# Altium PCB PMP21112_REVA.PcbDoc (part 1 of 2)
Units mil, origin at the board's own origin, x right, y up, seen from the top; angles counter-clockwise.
Board outline 3800 x 2750 mil, 4 copper layers (Top Layer, Signal Layer 1, Signal Layer 2, Bottom Layer), stack 68.2 mil thick; 110 components, 47 nets, 341 pads, 287 vias.
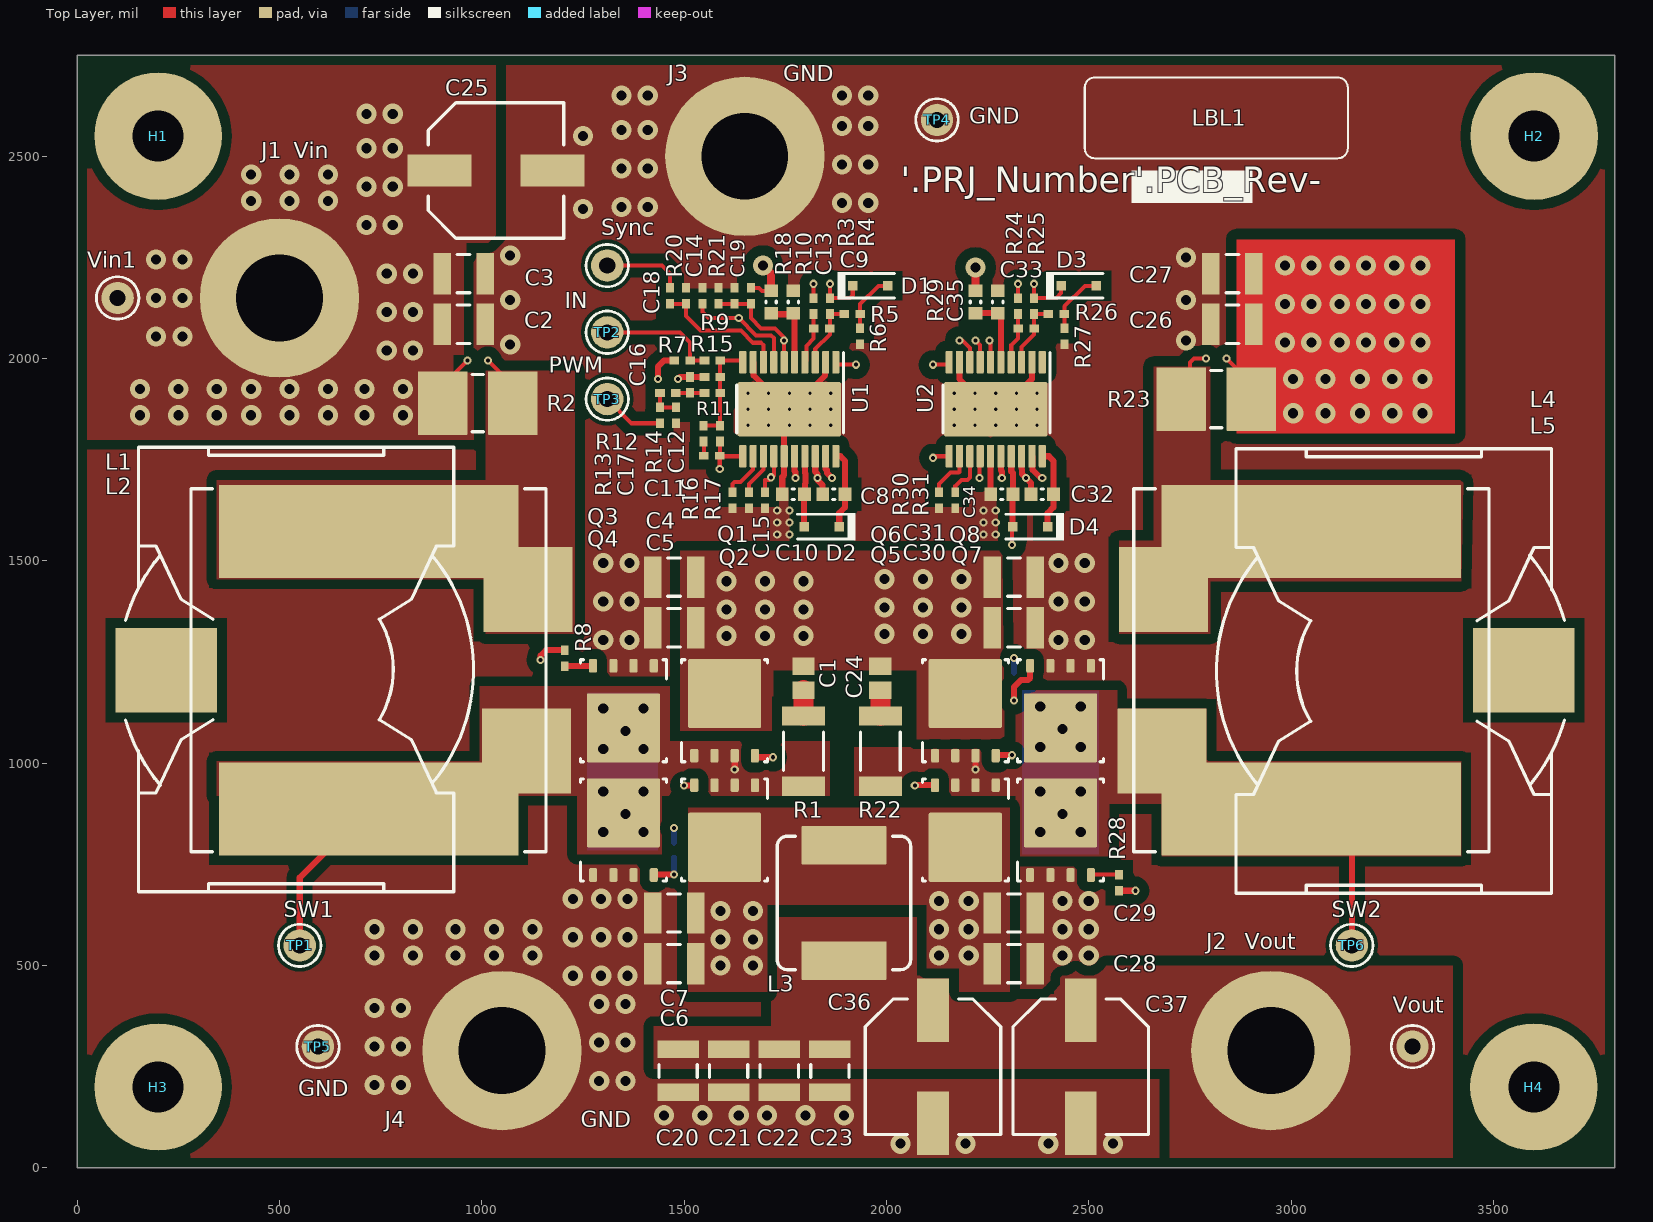
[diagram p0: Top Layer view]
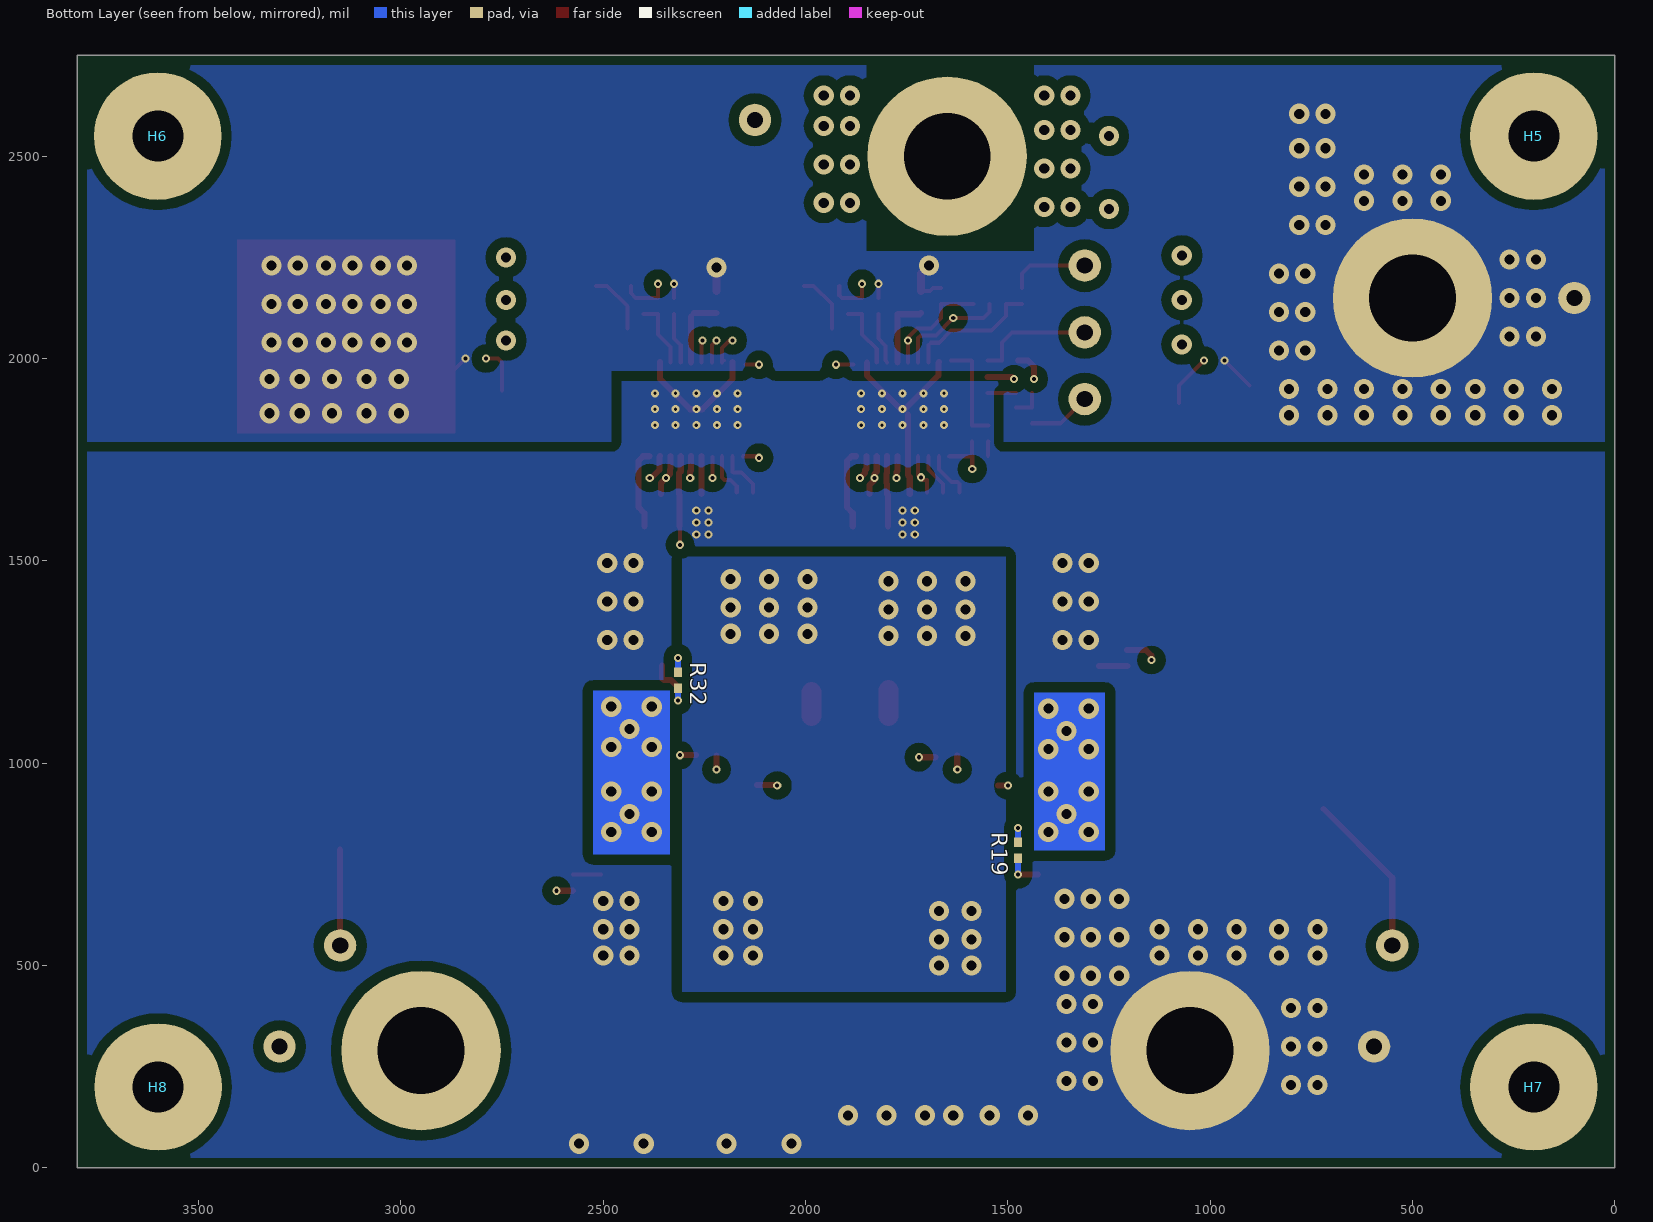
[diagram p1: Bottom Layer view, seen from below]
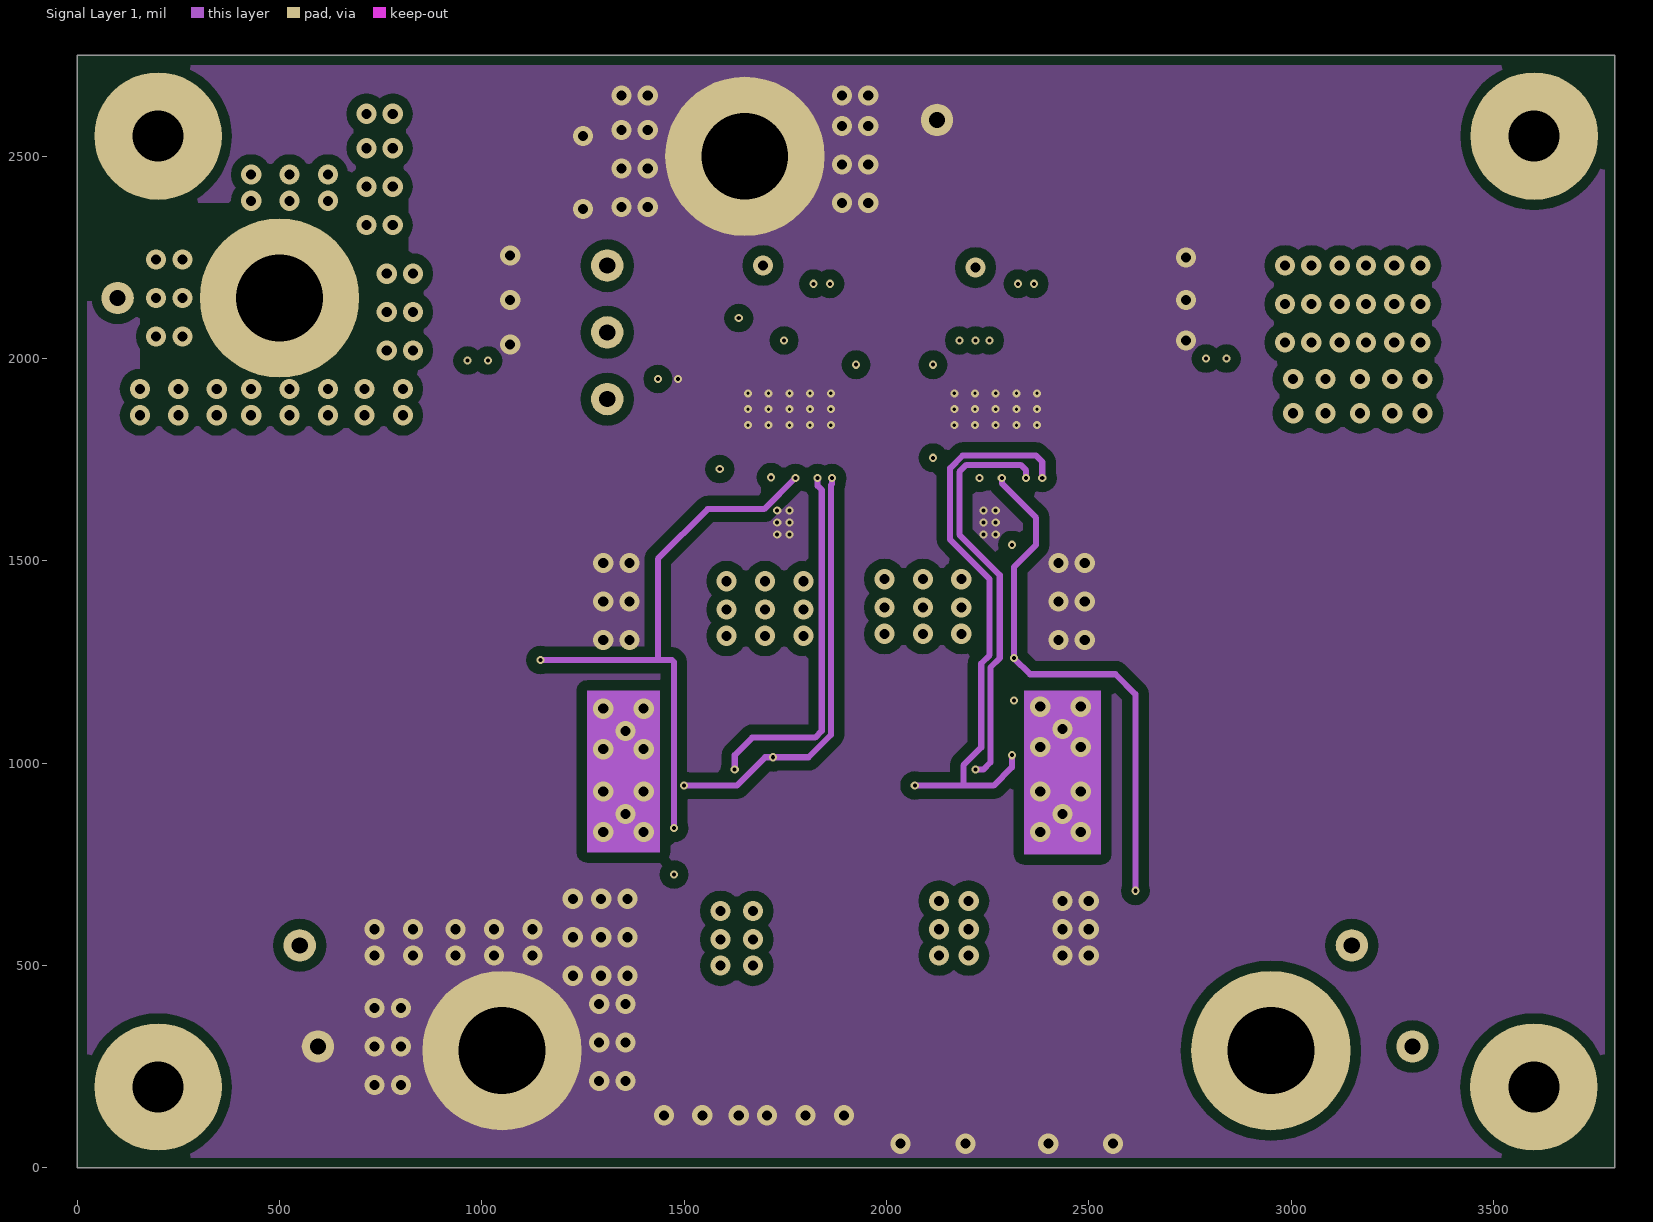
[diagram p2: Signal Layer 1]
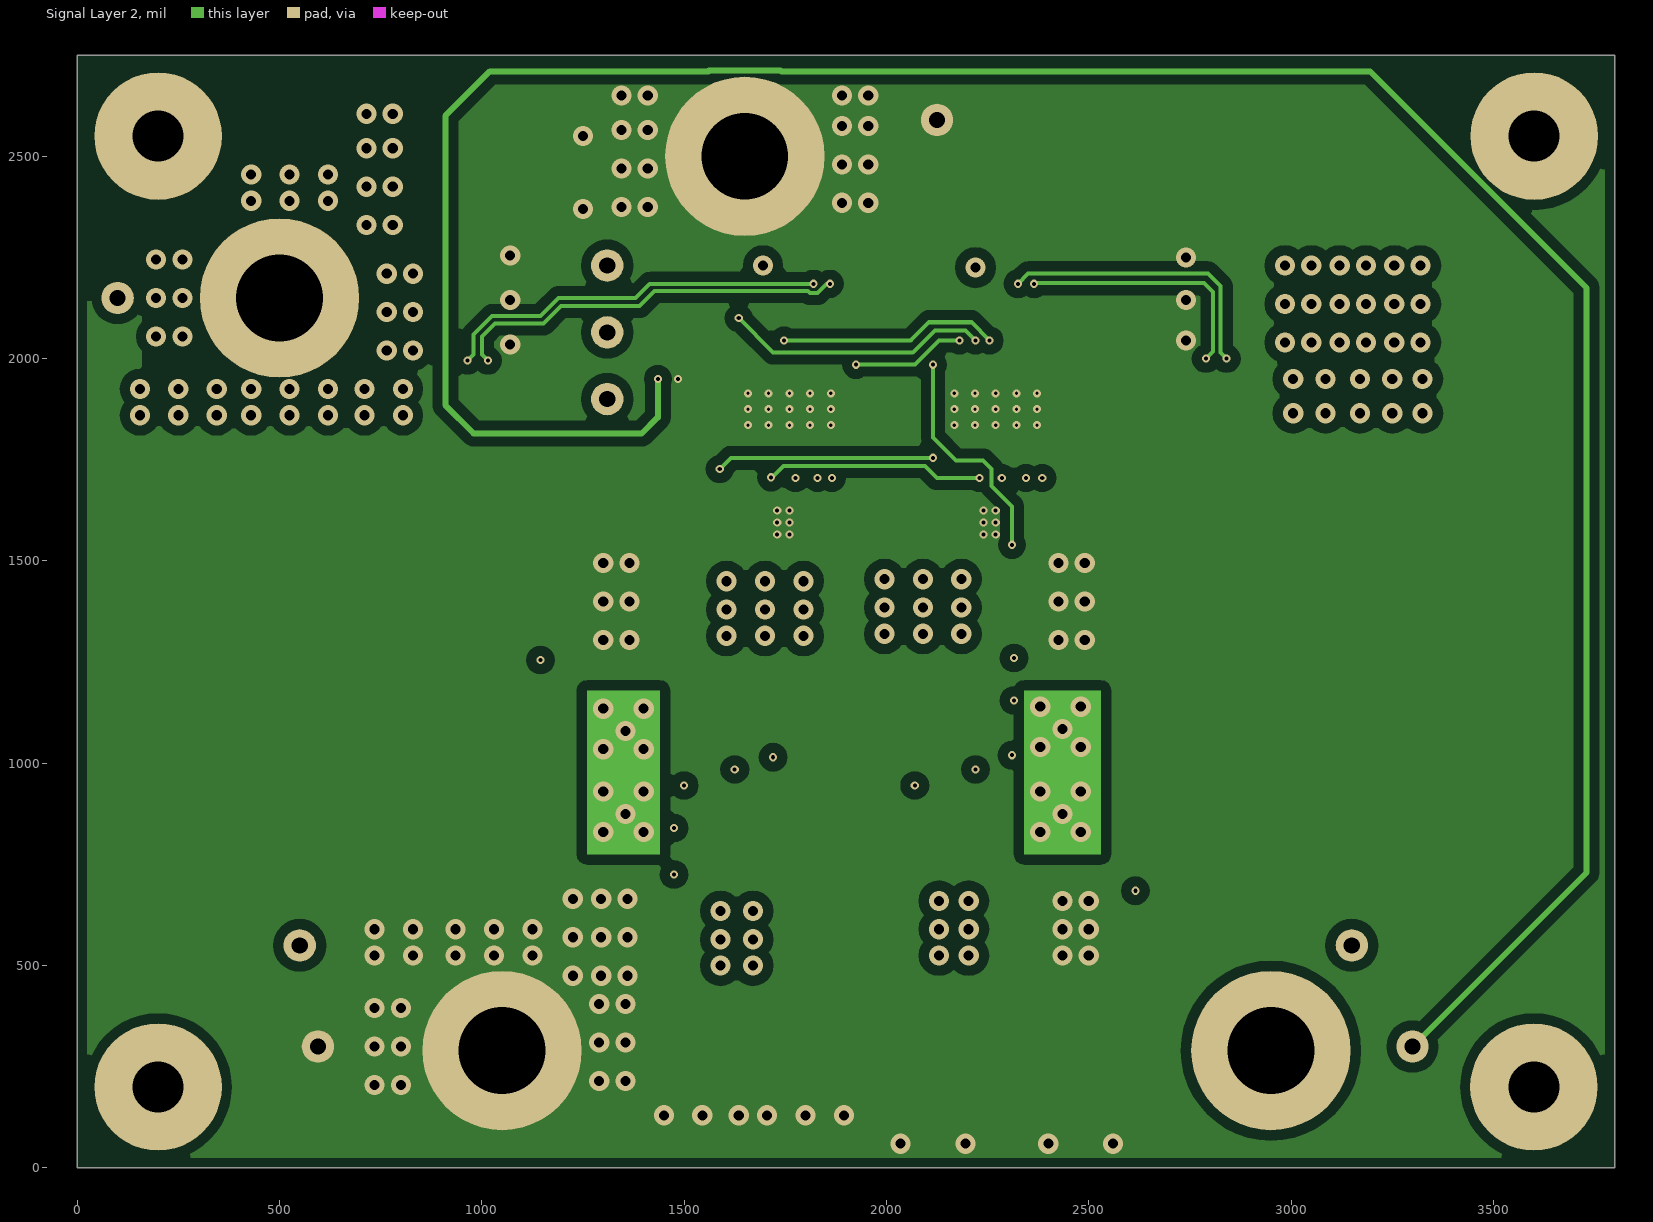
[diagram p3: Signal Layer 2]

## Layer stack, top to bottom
Top Solder: solder mask 0.4, Solder Resist, Dk 3.5
Top Layer: signal copper 2.8
Dielectric1: core 20, FR-4, Dk 4.8
Signal Layer 1: signal copper 2.8
Dielectric 2: dielectric 17, Dk 4.2
Signal Layer 2: signal copper 2.8
Dielectric 3: dielectric 20, FR-4, Dk 4.2
Bottom Layer: signal copper 2.8
Bottom Solder: solder mask 0.4, Solder Resist, Dk 3.5

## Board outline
0,0 3800,0 3800,2750 0,2750

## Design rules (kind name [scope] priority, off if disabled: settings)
AcuteAngle [All] p1: minimum=4.50000000000000E+0001 checktracksonly=FALSE
AssemblyTestPointUsage [All] p1: valid=2
BoardOutlineClearance BoardOutlineClearance_MountingHoles [OnCopper and InComponentClass('Mounting Holes')] p1: gap=40 ignorepadtopadclearanceinfootprint=FALSE
BoardOutlineClearance BoardOutlineClearance_Poly [OnCopper and IsPoly] p2: gap=25 ignorepadtopadclearanceinfootprint=FALSE
BoardOutlineClearance [OnCopper and Not InComponentClass('Logo') and not InComponentClass('FiducialMark') and not InRegion(1000,500,4000,800) and not InPoly] p3: gap=30 ignorepadtopadclearanceinfootprint=FALSE
Clearance Clearance_Keepouts [((IsTrack Or IsArc) And Not InPoly) And IsFree and IsKeepOut vs ((IsTrack Or IsArc) And Not InPoly) And IsFree and IsKeepOut] p1: gap=0 ignorepadtopadclearanceinfootprint=FALSE
Clearance Clearance_Poly [InPolygon] p2: gap=25 ignorepadtopadclearanceinfootprint=FALSE except(0: Arc-Hole Track-Hole SMDPad-Hole THPad-Hole Via-Hole Fill-Hole Poly-Hole Region-Hole Text-Hole)
Clearance Clearance_FiducialMark [IsKeepOut and InComponentClass('FiducialMark') vs IsPad and InComponentClass('FiducialMark')] p3: gap=0 ignorepadtopadclearanceinfootprint=FALSE
Clearance [All] p4: gap=7.87 ignorepadtopadclearanceinfootprint=FALSE except(0: Arc-Hole Track-Hole SMDPad-Hole THPad-Hole Via-Hole Fill-Hole Poly-Hole Region-Hole Text-Hole)
ComponentClearance ComponentClearance_Inductor [HasFootprint('SER2918H') vs HasFootprint('IHLP8787MZ')] p1: gap=0 collisioncheckmode=3 verticalgap=0 showdistances=FALSE
ComponentClearance ComponentClearance_MountingHoles_FiducialMarks [InComponentClass('Mounting Holes') vs InComponentClass('FiducialMark')] p2: gap=50 collisioncheckmode=3 verticalgap=10 showdistances=FALSE
ComponentClearance ComponentClearance_Shunt [InComponentClass('Header') vs InComponentClass('Shunt')] p3: gap=0 collisioncheckmode=3 verticalgap=0 showdistances=FALSE
ComponentClearance ComponentClearance_Logo [InComponentClass('Logo')] p4: gap=50 collisioncheckmode=3 verticalgap=10 showdistances=FALSE
ComponentClearance ComponentClearance_ScrewToNut [(HasFootprint('NY PMS 440 0025 PH')) vs (HasFootprint('Keystone_1902C'))] p5: gap=5 collisioncheckmode=3 verticalgap=10 showdistances=FALSE
ComponentClearance ComponentClearance_MountingHoles [InComponentClass('Mounting Holes')] p6: gap=130 collisioncheckmode=3 verticalgap=100000 showdistances=FALSE
ComponentClearance ComponentClearance_SmallPassives [HasFootprint('0201*') or HasFootprint('0402*') or HasFootprint('0508') or HasFootprint('0603*') or HasFootprint('0612') or HasFootprint('0805*') or HasFootprint('0815*') or HasFootprint('0830*') or HasFootprint('1206*') or HasFootprint('1210*') or HasFootprint('1808*') or HasFootprint('1812*') or HasFootprint('1825*') or HasFootprint('2010*') or HasFootprint('2220*') or HasFootprint('2225*') or HasFootprint('2512*') or HasFootprint('2728*') or HasFootprint('3518*') vs HasFootprint('0201*') or HasFootprint('0402*') or HasFootprint('0508') or HasFootprint('0603*') or HasFootprint('0612') or HasFootprint('0805*') or HasFootprint('0815*') or HasFootprint('0830*') or HasFootprint('1206*') or HasFootprint('1210*') or HasFootprint('1808*') or HasFootprint('1812*') or HasFootprint('1825*') or HasFootprint('2010*') or HasFootprint('2220*') or HasFootprint('2225*') or HasFootprint('2512*') or HasFootprint('2728*') or HasFootprint('3518*')] p7: gap=14.96 collisioncheckmode=3 verticalgap=10 showdistances=FALSE
ComponentClearance ComponentClearance_THtoSMT [IsThruComponent vs IsSMTComponent] p8: gap=40 collisioncheckmode=3 verticalgap=30 showdistances=FALSE
ComponentClearance ComponentClearance_THtoTH [IsThruComponent vs IsThruComponent] p9: gap=30 collisioncheckmode=3 verticalgap=30 showdistances=FALSE
ComponentClearance [All] p10: gap=30 collisioncheckmode=3 verticalgap=10 showdistances=FALSE
DiffPairsRouting [All] p1: maxlimit=100 minlimit=10 mostfreqgap=10 toplayer_minwidth=10 toplayer_maxwidth=15 toplayer_prefwidth=15 midlayer1_minwidth=10 midlayer1_maxwidth=15 midlayer1_prefwidth=15 midlayer2_minwidth=10 midlayer2_maxwidth=15 midlayer2_prefwidth=15 bottomlayer_minwidth=10 bottomlayer_maxwidth=15 bottomlayer_prefwidth=15 maxuncoupledlength=1000
FabricationTestPointUsage TestPointUsage [All] p1: valid=2 allowmultiple=FALSE
FabricationTestpoint Testpoint [All] p1: side=3 testpointundercomponent=TRUE minsize=40 maxsize=100 preferedsize=60 minholesize=0 maxholesize=40 preferedholesize=32 testpointgrid=1 allowsidetop=TRUE allowsidebottom=TRUE usegrid=TRUE gridtolerance=0.01
FanoutControl Fanout_LCC [IsLCC] p1: bgadir=Out bgaviamode=Centered fanoutstyle=Auto fanoutdirection=Alternating viagrid=1 // Fanout_LCC (Default Rule)
FanoutControl Fanout_BGA [IsBGA] p2: bgadir=Out bgaviamode=Centered fanoutstyle=Auto fanoutdirection=Alternating viagrid=1 // Fanout_BGA (Default Rule)
FanoutControl Fanout_Default [All] p4: bgadir=Out bgaviamode=Centered fanoutstyle=Auto fanoutdirection=Alternating viagrid=1 // Fanout_Default (Default Rule)
FanoutControl Fanout_Small [(CompPinCount < 5)] p5: bgadir=Out bgaviamode=Centered fanoutstyle=Auto fanoutdirection=OutThenIn viagrid=1 // Fanout_Small (Default Rule)
HoleSize [All] p1: absolutevalues=TRUE maxlimit=251 minlimit=7.87 maxpercent=80.000 minpercent=20.000
MinimumAnnularRing MinimumAnnularRing_ThermalPadVias [IsVia and InAnyComponent] p1: minimumring=5.91
MinimumAnnularRing [All] p2: minimumring=5
MinimumSolderMaskSliver MinimumSolderMaskSliver_Logo [InComponentClass('Logo') vs InComponentClass('Logo')] p1: minsoldermaskwidth=0.7
MinimumSolderMaskSliver [All] p2: minsoldermaskwidth=3.94
PlaneConnect [All] p1: planeconnectstyle=Direct reliefexpansion=10 reliefentries=4 reliefconductorwidth=10 reliefairgap=10
PolygonConnect [All] p1: connectstyle=Direct reliefconductorwidth=10 reliefentries=4 polygonreliefangle="90 Angle" airgapwidth=10
RoutingVias ThermalPadVias [IsVia and InAnyComponent] p1: holewidth=7.87 width=19.68 viastyle="Through Hole" minholewidth=7.87 minwidth=19.68 maxholewidth=12.99 maxwidth=23.62
RoutingVias [All] p2: holewidth=16 width=34 viastyle="Through Hole" minholewidth=7.87 minwidth=26 maxholewidth=40 maxwidth=65
SilkToBoardRegionClearance [Not ((IsComment or IsDesignator) And (Hide <> 'False')) and not InRegion(1000,500,4000,800)] p1:
SilkToSilkClearance SilkToSilkClearance_Pb-FreeLogo [(HasFootprint('Pb-Free_Overlay_Medium') OR HasFootprint('Pb-Free_Overlay_Small')) vs (HasFootprint('Pb-Free_Overlay_Medium') OR HasFootprint('Pb-Free_Overlay_Small'))] p1: silktosilkclearance=0
SilkToSilkClearance [All] p2: silktosilkclearance=3
SilkToSolderMaskClearance SilkToComponentPadClearance [(IsPad or IsFill or IsRegion) and InAnycomponent] p1: minsilkscreentomaskgap=5 clearancetoexposedcopper=TRUE
SilkToSolderMaskClearance "Silk to Solder Mask Opening" [All] p2: minsilkscreentomaskgap=4 clearancetoexposedcopper=FALSE
SolderMaskExpansion [All] p1: expansion=1.97
Width [All] p1: maxlimit=100 minlimit=6 preferedwidth=10 checkconnectedcopper=TRUE
15 further rules are at their usual default settings.

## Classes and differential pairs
component class PMP21112_REVA: C1 C2 C3 C4 C5 C6 C7 C8 C9 C10 C11 C12 C13 C14 C15 C16 C17 C18 C19 C20 C21 C22 C23 C24 C25 C26 C27 C28 C29 C30 C31 C32 C33 C34 C35 C36 C37 D1 D2 D3 D4 GND J1 J2 J3 J4 L1 L2 L3 L4 L5 Q1 Q2 Q3 Q4 Q5 Q6 Q7 Q8 R1 R2 R3 R4 R5 R6 R7 R8 R9 R10 R11 R12 R13 R14 R15 R16 R17 R18 R19 R20 R21 R22 R23 R24 R25 R26 R27 R28 R29 R30 R31 R32 Sync Sync1 TP1 TP2 TP3 TP4 TP5 TP6 U1 U2 Vin Vin1 Vout
component class PMP21112_REVA_Hardware: !PCB1 H1 H2 H3 H4 H5 H6 H7 H8 LBL1
component class "Mounting Holes": H1 H2 H3 H4
component class Label: LBL1

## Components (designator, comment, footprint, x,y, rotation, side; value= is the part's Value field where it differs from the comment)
C1 "GRM2165C2A471JA01D" 0805L 1795,1210 r270 top value=470pF
C2 "GRM32ER71K475KE14L" 1210_270L 955,2085 r0 top value=4.7uF
C3 "GRM32ER71K475KE14L" 1210_270L 955,2210 r0 top value=4.7uF
C4 "GRM32ER71K475KE14L" 1210_270L 1475,1460 r180 top value=4.7uF
C5 "GRM32ER71K475KE14L" 1210_270L 1475,1335 r180 top value=4.7uF
C6 "GRM32ER71K475KE14L" 1210_270L 1475,505 r180 top value=4.7uF
C7 "GRM32ER71K475KE14L" 1210_270L 1475,630 r180 top value=4.7uF
C8 "CGA3E3X7R1H474K080AE" 0603L 1870,1665 r180 top value=0.47uF
C9 "GRM1555C1H101JA01D" 0402L 1840,2075 r180 top value=100pF
C10 "GRM188R71E105KA12D" 0603L 1770,1665 r180 top value=1uF
C11 "GRM155R71C683KA88D" 0402L 1568.35,1760 r180 top value=0.068uF
C12 "GRM155R71H682KA88D" 0402L 1588.35,1815 r90 top value=6800pF
C13 "CGA3E3X7R1H474K080AE" 0603L 1770,2140 r90 top value=0.47uF
C14 "GRM155R71H104ME14D" 0402L 1545,2155 r90 top value=0.1uF
C15 "GRM155R71C224KA12D" 0402L 1700,1650 r270 top value=0.22uF
C16 "GRM155R70J105KA12D" 0402L 1515,1935 r90 top value=1uF
C17 "GRM155R70J105KA12D" 0402L 1480,1860 r270 top value=1uF
C18 "GRM1555C1H101JA01D" 0402L 1465,2155 r90 top value=100pF
C19 "GRM155R71C103KA01D" 0402L 1625,2155 r90 top value=0.01uF
C20 "GRM32ER71K475KE14L" 1210_270L 1485.32,239.68 r270 top value=4.7uF
C21 "GRM32ER71K475KE14L" 1210_270L 1610,239.68 r270 top value=4.7uF
C22 "GRM32ER71K475KE14L" 1210_270L 1735,239.68 r270 top value=4.7uF
C23 "GRM32ER71K475KE14L" 1210_270L 1860,239.68 r270 top value=4.7uF
C24 "GRM2165C2A471JA01D" 0805L 1985,1210 r270 top value=470pF
C25 "EEH-ZA1H680V" Panasonic_SMT_800x1020 1035,2465 r0 top value=68uF
C26 "GRM32ER71K475KE14L" 1210_270L 2855,2085 r180 top value=4.7uF
C27 "GRM32ER71K475KE14L" 1210_270L 2855,2210 r180 top value=4.7uF
C28 "GRM32ER71K475KE14L" 1210_270L 2315,505 r0 top value=4.7uF
C29 "GRM32ER71K475KE14L" 1210_270L 2315,630 r0 top value=4.7uF
C30 "GRM32ER71K475KE14L" 1210_270L 2315,1335 r0 top value=4.7uF
C31 "GRM32ER71K475KE14L" 1210_270L 2315,1460 r0 top value=4.7uF
C32 "CGA3E3X7R1H474K080AE" 0603L 2385,1665 r180 top value=0.47uF
C33 "GRM1555C1H101JA01D" 0402L 2345,2075 r180 top value=100pF
C34 "GRM188R71E105KA12D" 0603L 2285,1665 r180 top value=1uF
C35 "CGA3E3X7R1H474K080AE" 0603L 2275,2140 r90 top value=0.47uF
C36 "EEEFP1H101AP" Panasonic_SMT_800x1020 2115,250 r270 top value=100uF
C37 "EEEFP1H101AP" Panasonic_SMT_800x1020 2480,250 r270 top value=100uF
D1 "MMSZ5226BS-7-F" SOD-323 1960,2180 r0 top value=3.3V
D2 "PMEG6010CEJ,115" SOD-323F 1840,1585 r180 top value=60V
D3 "MMSZ5226BS-7-F" SOD-323 2475,2180 r0 top value=3.3V
D4 "PMEG6010CEJ,115" SOD-323F 2355,1585 r180 top value=60V
H1 "NY PMS 440 0025 PH" "NY PMS 440 0025 PH" 200,2550 r0 top locked
H2 "NY PMS 440 0025 PH" "NY PMS 440 0025 PH" 3600.79,2550 r0 top locked
H3 "NY PMS 440 0025 PH" "NY PMS 440 0025 PH" 200,200 r0 top locked
H4 "NY PMS 440 0025 PH" "NY PMS 440 0025 PH" 3600,200 r0 top locked
H5 "1902C" Keystone_1902C 200,2550 r180 bottom locked
H6 "1902C" Keystone_1902C 3600.79,2550 r180 bottom locked
H7 "1902C" Keystone_1902C 200,200 r180 bottom locked
H8 "1902C" Keystone_1902C 3600,200 r180 bottom locked
J1 "Vin" Keystone_575-4 500,2150 r0 top
J2 "Vout" Keystone_575-4 2950,290 r0 top
J3 "GND" Keystone_575-4 1650,2500 r0 top
J4 "GND" Keystone_575-4 1050,290 r0 top
L1 "DNP" SER2918H 545,1230 r180 top value=10uH
L2 "IHLP8787MZER100M5A" IHLP8787MZ 720,1230 r90 top value=10uH
L3 "IHLP3232DZERR82M11" IHLP-3232DZ 1895,655 r270 top value=820nH
L4 "DNP" SER2918H 3250,1230 r0 top value=10uH
L5 "IHLP8787MZER100M5A" IHLP8787MZ 3050,1230 r90 top value=10uH
LBL1 "Size: 0.65\" x 0.20 \"" Label_650x200 2815,2595 r0 top
Q1 "CSD18540Q5B" DNK0008A 1600,1130 r90 top value=60V
Q2 "CSD18540Q5B" DNK0008A 1600,835 r270 top value=60V
Q3 "CSD18540Q5B" DNK0008A 1350,1130 r270 top value=60V
Q4 "CSD18540Q5B" DNK0008A 1350,835 r90 top value=60V
Q5 "CSD18540Q5B" DNK0008A 2195,835 r270 top value=60V
Q6 "CSD18540Q5B" DNK0008A 2195,1130 r90 top value=60V
Q7 "CSD18540Q5B" DNK0008A 2430,835 r90 top value=60V
Q8 "CSD18540Q5B" DNK0008A 2430,1130 r270 top value=60V
R1 "ERJ-12ZYJ7R5U" 2010L 1795,1030 r270 top value=7.5
R2 "CRE2512-FZ-R002E-3" CRE2512-R1_R4 990,1890 r0 top value=0.002
R3 "CRCW0402100RFKED" 0402L 1820,2130 r90 top value=100
R4 "CRCW0402100RFKED" 0402L 1860,2130 r90 top value=100
R5 "CRCW040212K7FKED" 0402L 1915,2110 r0 top value=12.7k
R6 "CRCW040295K3FKED" 0402L 1935,2055 r90 top value=95.3k
R7 "CRCW040249R9FKED" 0402L 1495,1995 r0 top value=49.9
R8 "CRCW04020000Z0ED" 0402L 1205,1260 r90 top value=0
R9 "CRCW040249K9FKED" 0402L 1570,1995 r0 top value=49.9k
R10 "CRCW06033R30JNEA" 0603L 1715,2140 r270 top value=3.3
R11 "CRCW04021K74FKED" 0402L 1570,1915 r180 top value=1.74k
R12 "CRCW04021K00FKED" 0402L 1460,1915 r180 top value=1.00k
R13 "CRCW04021K00FKED" 0402L 1440,1860 r270 top value=1.00k
R14 "CRCW04025K11FKED" 0402L 1548.35,1815 r270 top value=5.11k
R15 "CRCW040213K0FKED" 0402L 1570,1955 r180 top value=13.0k
R16 "CRCW040297K6FKED" 0402L 1620,1650 r90 top value=97.6k
R17 "CRCW04020000Z0ED" 0402L 1660,1650 r90 top value=0
R18 "CRCW040249K9FKED" 0402L 1665,2155 r90 top value=49.9k
R19 "CRCW04020000Z0ED" 0402L 1475,785 r90 bottom value=0
R20 "CRCW040260K4FKED" 0402L 1505,2155 r270 top value=60.4k
R21 "CRCW04029K53FKED" 0402L 1585,2155 r270 top value=9.53k
R22 "ERJ-12ZYJ7R5U" 2010L 1985,1030 r270 top value=7.5
R23 "CRE2512-FZ-R002E-3" CRE2512-R1_R4 2815,1900 r180 top value=0.002
R24 "CRCW0402100RFKED" 0402L 2325,2130 r90 top value=100
R25 "CRCW0402100RFKED" 0402L 2365,2130 r90 top value=100
R26 "CRCW040212K7FKED" 0402L 2420,2110 r0 top value=12.7k
R27 "CRCW040295K3FKED" 0402L 2440,2055 r90 top value=95.3k
R28 "CRCW04020000Z0ED" 0402L 2575,705 r270 top value=0
R29 "CRCW06033R30JNEA" 0603L 2220,2140 r270 top value=3.3
R30 "CRCW040297K6FKED" 0402L 2130,1650 r90 top value=97.6k
R31 "CRCW04020000Z0ED" 0402L 2170,1650 r90 top value=0
R32 "CRCW04020000Z0ED" 0402L 2315,1205 r90 bottom value=0
Sync "5002" Keystone5002 1310,2230 r90 top value=White
TP1 "SW1" Keystone5002 550,550 r90 top value=White
TP2 "IN" Keystone5002 1310,2065 r90 top value=White
TP3 "PWM" Keystone5002 1310,1900 r90 top value=White
TP4 "GND" Keystone5001 2125,2590 r90 top value=Black
TP5 "GND" Keystone5001 595,300 r90 top value=Black
TP6 "SW2" Keystone5002 3150,550 r90 top value=White
U1 "LM25122QPWPTQ1" PWP0020A_N 1760,1875 r270 top
U2 "LM25122QPWPTQ1" PWP0020A_N 2270,1875 r270 top
Vin1 "5000" Keystone5000 100,2150 r90 top value=Red
Vout "5000" Keystone5000 3300,300 r90 top value=Red

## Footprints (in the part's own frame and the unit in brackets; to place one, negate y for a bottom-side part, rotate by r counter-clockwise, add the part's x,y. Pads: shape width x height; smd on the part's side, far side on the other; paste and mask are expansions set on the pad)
0402L [mm] "0402 from SM-752 data"
  rect 0.6x0.5 smd: 1(-0.5,0) 2(0.5,0)
  body extent -0.55,-0.3 0.55,0.3, height 0.6
0603L [mm] "0603 from SM-752 data"
  rect 0.8x0.85 smd: 1(-0.7,0) 2(0.7,0)
  silkscreen extent -0.07,-0.33 0.07,0.33, body extent -0.87,-0.47 0.87,0.47, height 1
0805L [mm] "0805 from SM-752 data"
  rect 1.1x1.4 smd: 1(-0.75,0) 2(0.75,0)
  body extent -1.1,-0.72 1.1,0.72, height 1.45
1210_270L [mm] "1210"
  rect 1.1x2.6 smd: 1(-1.35,0) 2(1.35,0)
  silkscreen extent -0.4,-1.2 0.4,1.2, body extent -1.7,-1.35 1.7,1.35, height 2.7
2010L [mm]
  rect 1.2x2.7 smd: 1(-2.2,0) 2(2.2,0)
  silkscreen extent -1.2,-1.25 1.2,1.25, body extent -2.73,-1.45 2.73,1.45, height 1.66
CRE2512-R1_R4 [mm] "SMD, 2-Leads, Body 6.45x3.35mm"
  rrect3% 3.1x4 smd: 1(-2.2,0) 2(2.2,0)
  silkscreen extent -0.35,-1.8 0.35,1.8, body extent -3.32,-1.77 3.33,1.78, height 0.9
DNK0008A [mm] "SON, 8-Leads, Body 5x6mm"
  rrect39% 0.86x0.51 smd paste-0.05 mask-0.05: 1(-2.82,1.905) 2(-2.82,0.635) 3(-2.82,-0.635) 4(-2.82,-1.905) 5(2.82,-1.905) 6(2.82,-0.635) 7(2.82,0.635) 8(2.82,1.905)
  rrect8% 1.48x1.27 on Top Paste: 9(-0.18,1.47) 9(-0.18,0) 9(-0.18,-1.47) 9(1.5,-1.47) 9(1.5,0) 9(1.5,1.47)
  rrect5% 4.34x4.6 smd paste-3 mask-0.05: 9(1.08,0)
  silkscreen extent -3.2,-2.7 3.2,2.7, body extent -3.05,-2.55 3.05,2.55, height 1.06
IHLP8787MZ [mm] "SMD, 2-Leads, Body 22x22.48mm"
  rect 5.84x18.8 smd: 1(-8.7,0) 2(8.7,0)
  silkscreen extent -11.39,-11.15 11.39,11.15, body extent -11.39,-11.15 11.39,11.15, height 13
IHLP-3232DZ [mil] "VISHAY"
  rrect5% 95x210 smd: 1(-142.5,0) 2(142.5,0)
  silkscreen extent -165,-165 165,165, body extent -169,-161 169,161, height 154
Keystone5000 [mil] "For Keystone 500x miniature loop terminals"
  round 80 hole 40: 1(0,0)
  silkscreen extent -52,-52 52,52, body extent -49,-49 49,49, height 182
Keystone5001 [mil] "For Keystone 500x miniature loop terminals"
  round 80 hole 40: 1(0,0)
  silkscreen extent -52,-52 52,52, body extent -49,-49 49,49, height 182
Keystone5002 [mil] "For Keystone 500x miniature loop terminals"
  round 80 hole 40: 1(0,0)
  silkscreen extent -52,-52 52,52, body extent -49,-49 49,49, height 182
Keystone_575-4 [mm] "Banana Jack"
  round 10 hole 5.45: 1(0,0)
  body extent -3.95,-3.95 3.92,3.93, height 2.36
Keystone_1902C [mil] "Hex Standoff, 4-40 threaded, nylon"
  body extent -145,-126 146,126, height 501
Label_650x200 [mil] "Thermal Transfer Label"
  silkscreen extent -325,-100 325,100, body extent -325,-100 325,100, height 1
"NY PMS 440 0025 PH" [mm] "4-40 nylon screw and mounting hole"
  round 8 hole 3.2: 1(0,0)
  body extent -3.3,-3.3 3.3,3.3, height 2.69
Panasonic_SMT_800x1020 [mm] "SMD, 2-Leads, Dia 8mm"
  rect 4x2 smd: 1(-3.55,0) 2(3.55,0)
  silkscreen extent -4.25,-4.25 4.25,4.25, body extent -4.25,-4.25 4.25,4.25, height 10.51
PWP0020A_N [mm] "TSOP, 20-Leads, Body 6.5x4.4mm, Pitch 0.65mm, Exposed Pad, IPC Medium Density"
  rrect22% 1.4x0.45 smd: 1(-2.95,2.925) 2(-2.95,2.275) 3(-2.95,1.625) 4(-2.95,0.975) 5(-2.95,0.325) 6(-2.95,-0.325) 7(-2.95,-0.975) 8(-2.95,-1.625) 9(-2.95,-2.275) 10(-2.95,-2.925) 11(2.95,-2.925) 12(2.95,-2.275) 13(2.95,-1.625) 14(2.95,-0.975) 15(2.95,-0.325) 16(2.95,0.325) 17(2.95,0.975) 18(2.95,1.625) 19(2.95,2.275) 20(2.95,2.925)
  rrect6% 3.4x6.5 smd paste-2 mask-2: 21(0,0)
  rrect3% 3.15x4.35 on Top Paste: 21(0,0)
  rrect3% 3.15x4.35 on Top Solder: 21(0,0)
  silkscreen extent -3.55,-3.3 1.5,3.4, body extent -3.21,-3.25 3.21,3.25, height 1
SER2918H [mm] "COILCRAFT"
  rect 5.59x5.33 smd: 1(-14.355,5.075) 2(-14.455,-5.075)
  rect 6.35x5.28 smd: 3(8.25,0)
  silkscreen extent -11.04,-14 10.81,13.9, body extent -16.7,-14.05 11.22,13.85, height 17.82
SOD-323 [mm] "NXP recommended land pattern"
  rect 0.6x0.6 smd paste-0.05: 1(-1.1,0) 2(1.1,0)
  silkscreen extent -2.06,-0.86 1.53,0.86, body extent -1.3,-0.67 1.3,0.68, height 1.1
SOD-323F [mm] "NXP recommended land pattern"
  rect 0.6x0.6 smd paste-0.05: 1(-1.1,0) 2(1.1,0)
  silkscreen extent -2.13,-0.86 1.53,0.86, body extent -1.35,-0.67 1.35,0.68, height 0.79

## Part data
C1 C24: "CAP, CERM, 470pF, 100V, +/-5%, C0G/NP0, 0805", Alternate Manufacturer=-, Cap_Case=0805, Manufacturer=MuRata, Supplier Part Number 1=490-1611-1-ND, TempCo=C0G/NP0, Tolerance_%=5, Value1=?, Value2=100V, ValueDisplayed=470pF
C2 C3 C4 C5 C6 C7 C20 C21 C22 C23 C26 C27 C28 C29 C30 C31: "CAP, CERM, 4.7 µF, 80 V, +/- 10%, X7R, 1210", Cap_Case=1210, Manufacturer=MuRata, Supplier Part Number 1=490-9972-1-ND, TempCo=X7R, Tolerance_%=10, Value1=Unknown, Value2=80V, ValueDisplayed=4.7µF
C8 C13 C32 C35: "CAP, CERM, 0.47 µF, 50 V,+/- 10%, X7R, AEC-Q200 Grade 1, 0603", Cap_Case=0603, Manufacturer=TDK, Supplier Part Number 1=445-172475-1-ND, TempCo=X7R, Tolerance_%=10, Value2=50V, ValueDisplayed=0.47µF
C9 C18 C33: "CAP, CERM, 100 pF, 50 V,+/- 5%, C0G/NP0, 0402", Cap_Case=0402, Manufacturer=MuRata, Supplier Part Number 1=81-GRM1555C1H101JA1D, TempCo=C0G/NP0, Tolerance_%=5, Value2=50V, ValueDisplayed=100pF
C10 C34: "CAP, CERM, 1uF, 25V, +/-10%, X7R, 0603", Alternate Manufacturer=-, Cap_Case=0603, Manufacturer=MuRata, Supplier Part Number 1=490-5307-1-ND, TempCo=X7R, Tolerance_%=10, Value1=?, Value2=25V, ValueDisplayed=1µF
C11: library part GRM155R71H104ME14D, "CAP, CERM, 0.1 µF, 50 V,+/- 20%, X7R, 0402", Cap_Case=0402, Manufacturer=MuRata, Supplier Part Number 1=490-3259-1-ND, TempCo=X7R, Tolerance_%=10, Value2=16V, ValueDisplayed=0.068µF
C12: library part GRM155R71H103KA88D, "CAP, CERM, 0.01 µF, 50 V,+/- 10%, X7R, 0402", Cap_Case=0402, Manufacturer=MuRata, Supplier Part Number 1=490-4515-1-ND, TempCo=X7R, Tolerance_%=10, Value2=50V, ValueDisplayed=6800pF
C14: library part GRM155R71C224KA12D, "CAP, CERM, 0.22 µF, 16 V,+/- 10%, X7R, 0402", Cap_Case=0402, Manufacturer=MuRata, Supplier Part Number 1=490-10701-1-ND, TempCo=X7R, Tolerance_%=20, Value2=50V, ValueDisplayed=0.1µF
C15: "CAP, CERM, 0.22 µF, 16 V,+/- 10%, X7R, 0402", Cap_Case=0402, Manufacturer=MuRata, Supplier Part Number 1=490-5418-1-ND, TempCo=X7R, Tolerance_%=10, Value2=16V, ValueDisplayed=0.22µF
C16 C17: library part GRM155R71H104ME14D, "CAP, CERM, 0.1 µF, 50 V,+/- 20%, X7R, 0402", Cap_Case=0402, Manufacturer=MuRata, Supplier Part Number 1=490-10024-1-ND, TempCo=X7R, Tolerance_%=10, Value2=6.3V, ValueDisplayed=1µF
C19: library part CMP-0006639-2, "CAP, CERM, 0.01 uF, 16 V, +/- 10%, X7R, 0402", Cap_Case=0402, Manufacturer=MuRata, Supplier Part Number 1=490-1313-1-ND, TempCo=X7R, Tolerance_%=10%, Value1=Unknown, Value2=16V, ValueDisplayed=0.01uF
C25: library part CMP-0077288-1, "CAP, Aluminum Polymer, 68 µF, 50 V,+/- 20%, 0.03 ohm, AEC-Q200 Grade 2, D8xL10.2mm SMD", Cap_Case=8x10.2mm, Manufacturer=Panasonic, Supplier Part Number 1=P19826CT-ND, Tolerance_%=20%, Value1="0.03 ohm", Value2=50V, ValueDisplayed=68µF
C36 C37: library part CMP-0078149-1, "CAP, AL, 180 µF, 50 V, +/- 20%, 0.34 ohm, AEC-Q200 Grade 2, SMD", Cap_Case=8x10.2mm, Manufacturer=Panasonic, Supplier Part Number 1=P19726CT-ND, Tolerance_%=20%, Value1="0.18 ohm", Value2=50V, ValueDisplayed=100µF
D1 D3: library part CMP-0005776-1, "Diode, Zener, 1.8 V, 500 mW, SOD-123", Manufacturer="Diodes Inc.", Power_W=0.2, Supplier Part Number 1=MMSZ5226BS-FDICT-ND, Value1=0.2W
D2 D4: "Diode, Schottky, 60 V, 1 A, SOD-323F", Manufacturer=Nexperia, Supplier Part Number 1=568-4138-1-ND, Value1=1A, Value2=0.66V
H1 H2 H3 H4: "Machine Screw, Round, #4-40 x 1/4, Nylon, Philips panhead", DigiKeyPartNumber=H542-ND, Manufacturer="B&F Fastener Supply"
H5 H6 H7 H8: "Standoff, Hex, 0.5\"L #4-40 Nylon", Manufacturer=Keystone, Supplier Part Number 1=36-1902C-ND
J1 J2 J3 J4: library part 575-4, "Standard Banana Jack, Uninsulated, 5.5mm", Alternate Manufacturer=Any, Alternate PartNumber=Equivalent, Manufacturer=Keystone, Supplier Part Number 1=575-4K-ND
L1 L4: library part SER2918H-103KL, "Inductor, Shielded E Core, Ferrite, 10 µH, 28 A, 0.0026 ohm, SMD", Manufacturer=Coilcraft, Value1="0.0026 ohm", Value2=28A, ValueDisplayed=10µH
L2 L5: library part CMP-0063541-1, "Inductor, Shielded, 10 uH, 28 A, 0.00404 ohm, AEC-Q200 Grade 0, SMD", Manufacturer=Vishay-Dale, Supplier Part Number 1=IHLP8787MZER100M5A-ND, Value1="0.00404 ohm", Value2=28A, ValueDisplayed=10uH
L3: library part CMP-0061058-1, "Inductor, Shielded, Composite, 800 nH, 25.8 A, 0.00208 ohm, SMD", Manufacturer=Vishay-Dale, Supplier Part Number 1=541-1361-1-ND, Value1="0.00388 ohm", Value2=15A, ValueDisplayed=820nH
LBL1: library part THT-14-423-10, "Thermal Transfer Printable Labels, 0.650\" W x 0.200\" H - 10,000 per roll", Manufacturer=Brady, Supplier Part Number 1=97C5133
Q1 Q2 Q3 Q4 Q5 Q6 Q7 Q8: library part CMP-0067552-1, "MOSFET, N-CH, 60 V, 17.9 A, AEC-Q101, 8-PowerTDFN", Alternate Manufacturer=None, Manufacturer="Texas Instruments", Supplier Part Number 1=296-41076-1-ND, Value1="0.0033 ohm", Value2="41 nC"
R1 R22: "RESISTOR 7.5 OHM 3/4W 5% 2010", Alternate Manufacturer=-, Manufacturer=Panasonic, Power_W=1, Supplier Part Number 1=P7.5WCT-ND, TempCo="-100 /+600 ppm/C", Tolerance_%=5, Value1=5%, Value2=1W, Value_Code=7R50
R2 R23: library part CMP-0015748-2, "RES, 0.001, 1%, 3 W, AEC-Q200 Grade 0, 2512", Manufacturer=Bourns, Power_W=3, Supplier Part Number 1=CRE2512-FZ-R002E-3CT-ND, TempCo="50 ppm/C", Tolerance_%=1, Value1=1%, Value2=3W, Value_Code=2L000, ValueDisplayed=0.002
R3 R4 R24 R25: "RES, 100, 1%, 0.063 W, 0402", Manufacturer=Vishay-Dale, Power_W=0.063, Supplier Part Number 1=541-100LCT-ND, TempCo="100 ppm/C", Tolerance_%=1, Value1=1%, Value2=0.063W, Value_Code=100R, ValueDisplayed=100
R5 R26: library part CRCW04026K49FKED, "RES, 6.49 k, 1%, 0.063 W, 0402", Manufacturer=Vishay-Dale, Power_W=0.063, Supplier Part Number 1=541-12.7KLCT-ND, TempCo="100 ppm/C", Tolerance_%=1, Value1=1%, Value2=0.063W, Value_Code=12k7, ValueDisplayed=12.7k
R6 R27: library part CRCW040210K0FKED, "RES, 10.0 k, 1%, 0.063 W, 0402", Manufacturer=Vishay-Dale, Power_W=0.063, Supplier Part Number 1=541-95.3KLCT-ND, TempCo="100 ppm/C", Tolerance_%=1, Value1=1%, Value2=0.063W, Value_Code=95k3, ValueDisplayed=95.3k
R7: "RES, 49.9, 1%, 0.063 W, 0402", Manufacturer=Vishay-Dale, Power_W=0.063, Supplier Part Number 1=541-49.9LCT-ND, TempCo="100 ppm/C", Tolerance_%=1, Value1=1%, Value2=0.063W, Value_Code=49R9, ValueDisplayed=49.9
R8 R17 R19 R28 R31 R32: "RES, 0, 5%, 0.063 W, 0402", Manufacturer=Vishay-Dale, Power_W=0.063, Supplier Part Number 1=541-0.0JCT-ND, TempCo="200 ppm/C", Tolerance_%=5, Value1=5%, Value2=0.063W, Value_Code=0000, ValueDisplayed=0
R9 R18: "RES, 49.9 k, 1%, 0.063 W, 0402", Manufacturer=Vishay-Dale, Power_W=0.063, Supplier Part Number 1=541-49.9KLCT-ND, TempCo="100 ppm/C", Tolerance_%=1, Value1=1%, Value2=0.063W, Value_Code=49k9, ValueDisplayed=49.9k
R10 R29: "RES, 3.3, 5%, 0.1 W, 0603", Manufacturer=Vishay-Dale, Power_W=0.1, Supplier Part Number 1=541-3.3GCT-ND, TempCo="200 ppm/C", Tolerance_%=5, Value1=5%, Value2=0.1W, Value_Code=3R30, ValueDisplayed=3.3
R11: library part CRCW04022K87FKED, "RES, 2.87 k, 1%, 0.063 W, 0402", Manufacturer=Vishay-Dale, Power_W=0.063, Supplier Part Number 1=541-1.74KLCT-ND, TempCo="100 ppm/C", Tolerance_%=1, Value1=1%, Value2=0.063W, Value_Code=1k74, ValueDisplayed=1.74k
R12 R13: "RES, 1.00 k, 1%, 0.063 W, 0402", Manufacturer=Vishay-Dale, Power_W=0.063, Supplier Part Number 1=541-1.00KLCT-ND, TempCo="100 ppm/C", Tolerance_%=1, Value1=1%, Value2=0.063W, Value_Code=1k00, ValueDisplayed=1.00k
R14: "RES, 5.11 k, 1%, 0.063 W, 0402", Manufacturer=Vishay-Dale, Power_W=0.063, Supplier Part Number 1=541-5.11KLCT-ND, TempCo="100 ppm/C", Tolerance_%=1, Value1=1%, Value2=0.063W, Value_Code=5k11, ValueDisplayed=5.11k
R15: library part CRCW04021K96FKED, "RES, 1.96 k, 1%, 0.063 W, 0402", Manufacturer=Vishay-Dale, Power_W=0.063, Supplier Part Number 1=541-13.0KLCT-ND, TempCo="100 ppm/C", Tolerance_%=1, Value1=1%, Value2=0.063W, Value_Code=13k0, ValueDisplayed=13.0k
R16 R30: library part CRCW0402174KFKED, "RES, 174 k, 1%, 0.063 W, 0402", Manufacturer=Vishay-Dale, Power_W=0.063, Supplier Part Number 1=541-97.6KLCT-ND, TempCo="100 ppm/C", Tolerance_%=1, Value1=1%, Value2=0.063W, Value_Code=97k6, ValueDisplayed=97.6k
R20: "RES, 60.4 k, 1%, 0.063 W, 0402", Manufacturer=Vishay-Dale, Power_W=0.063, Supplier Part Number 1=541-60.4KLCT-ND, TempCo="100 ppm/C", Tolerance_%=1, Value1=1%, Value2=0.063W, Value_Code=60k4, ValueDisplayed=60.4k
R21: "RES, 9.53 k, 1%, 0.063 W, 0402", Manufacturer=Vishay-Dale, Power_W=0.063, Supplier Part Number 1=541-9.53KLCT-ND, TempCo="100 ppm/C", Tolerance_%=1, Value1=1%, Value2=0.063W, Value_Code=9k53, ValueDisplayed=9.53k
Sync: "Test Point, TH, Miniature, White", Alternate Manufacturer=Any, Alternate PartNumber=Equivalent, DigiKeyPartNumber=5002K-ND, Manufacturer=Keystone
TP1 TP2 TP3 TP6: library part 5002, "Test Point, TH, Miniature, White", Alternate Manufacturer=Any, Alternate PartNumber=Equivalent, DigiKeyPartNumber=5002K-ND, Manufacturer=Keystone
TP4 TP5: library part 5001, "Test Point, TH, Miniature, Black", Alternate Manufacturer=-, DigiKeyPartNumber=5001K-ND, Manufacturer=Keystone
U1 U2: "Automotive Grade, 3-42V Wide Vin, Synchronous Boost Controller with Multiphase Capability, PWP0020A (TSSOP-20)", Alternate Manufacturer="Texas Instruments"
Vin1 Vout: "Test Point, TH, Miniature, Red", Alternate Manufacturer=-, DigiKeyPartNumber=5000K-ND, Manufacturer=Keystone

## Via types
v1: diameter 50, hole 25, Top Layer to Bottom Layer, 205 vias
v2: diameter 20, hole 10, Top Layer to Bottom Layer, 52 vias
v3: diameter 19.68, hole 7.87, Top Layer to Bottom Layer, 18 vias
v4: diameter 19.68, hole 7.87, Top Layer to Bottom Layer, tented both sides, 12 vias

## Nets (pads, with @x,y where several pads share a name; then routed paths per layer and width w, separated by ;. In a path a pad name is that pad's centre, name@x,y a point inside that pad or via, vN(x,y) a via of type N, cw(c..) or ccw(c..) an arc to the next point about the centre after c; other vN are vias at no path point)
BST1: C8.1 D2.1 U1.20 | length 195.5
  Top Layer w15: U1.20@1875.16,1758.86 1886.14,1758.86 1897.56,1747.44 C8.1@1897.56,1665 1897.56,1632.56 1883.31,1618.31 D2.1@1883.31,1585
BST2: C32.1 D4.1 U2.20 | length 200.5
  Top Layer w15: U2.20@2385.16,1758.86 2401.14,1758.86 2412.56,1747.44 C32.1@2412.56,1665 2412.56,1632.56 2398.31,1618.31 D4.1@2398.31,1585
COMP: C11.1 C12.1 U1.11 U2.11 | length 700.1
  Top Layer w10: v2(1588.03,1726.97) C11.1@1588.03,1760 ; C12.1@1588.35,1795.32 1589.17,1794.49 1589.17,1758.86 U1.11@1644.84,1758.86 ; v2@2118.86,1758.86 U2.11@2154.84,1758.86
  Signal Layer 2 w10: v2(1588.03,1726.97) 1616.06,1755 v2(2115,1755)
CSN1: C9.1 R4.1 R5.1 U1.3 | length 169.5
  Top Layer w10: U1.3@1823.98,1991.14 1823.98,2023.98 1860,2060 R4.1@1860,2110.32 1895,2110.32 R5.1@1895.32,2110
CSN2: C33.1 R25.1 R26.1 U2.3 | length 167.5
  Top Layer w10: U2.3@2333.98,1991.14 2333.98,2028.98 2365,2060 R25.1@2365,2110.32 2400,2110.32 R26.1@2400.32,2110
CSP1: C9.2 R3.1 U1.4 | length 128.1
  Top Layer w10: U1.4@1798.39,1991.14 1802.24,1995 1802.24,2031.57 1820,2049.33 R3.1@1820,2110.32
CSP2: C33.2 R24.1 U2.4 | length 126.1
  Top Layer w10: U2.4@2308.39,1991.14 2308.39,2033.39 2325,2050 R24.1@2325,2110.32
FB: C12.2 R9.2 R11.1 R14.1 R15.1 U1.10 | length 252.2
  Top Layer w10: R14.1@1548.35,1834.68 C12.2@1588.35,1834.69 1588.35,1993.66 R9.2@1589.69,1995 U1.10@1640.98,1995
GND: C2.2 C3.2 C4.2 C5.2 C6.2 C7.2 C10.2 C13.2 C14.2 C15.2 C16.2 C17.2 C19.2 C20.2 C21.2 C22.2 C23.2 C25.2 C26.2 C27.2 C28.2 C29.2 C30.2 C31.2 C34.2 C35.2 C36.2 C37.2 J3.1 J4.1 Q3.1 Q3.2 Q3.3 Q4.1 Q4.2 Q4.3 Q7.1 Q7.2 Q7.3 Q8.1 Q8.2 Q8.3 R6.1 R15.2 R16.1 R17.1 R20.1 R21.1 R27.1 R30.1 R31.1 TP4.1 TP5.1 U1.2 U1.9 U1.15 U1.21@1760,1875 U2.2 U2.9 U2.15 U2.21@2270,1875 | length 994.4
  Top Layer w15: v2(1485,1950) 1489.69,1954.69 C16.2@1515,1954.69 R15.2@1550,1954.69 ; U1.9@1670.43,1991.14 1671.79,1989.78 1671.79,1958.36 1755.15,1875 v3(1760,1875) 1764.85,1875 1848.21,1958.36 U1.2@1848.21,1989.78 ; C10.2@1742.44,1665 1742.44,1707.44 1747.2,1712.2 U1.15@1747.2,1758.86 U1.21@1747.2,1862.2 ; U2.9@2180.43,1991.14 2180.43,1949.57 2255,1875 v3(2270,1875) 2285,1875 2359.57,1949.57 U2.2@2359.57,1991.14 ; U2.15@2257.2,1758.86 2257.44,1758.62 C34.2@2257.44,1665
  other v1: 2035,60 2195,60 2400,60 2560,60 1450,130 1545,130 1635,130 1705,130 1800,130 1895,130 735,205 800,205 1290,215 1355,215 735,300 800,300 1290,310 1355,310 735,395 800,395 1290,405 1355,405 1225,475 1295,475 1360,475 735,525 830,525 935,525 1030,525 1125,525 2435,525 2500,525 1225,570 1295,570 1360,570 735,590 830,590 935,590 1030,590 1125,590 2435,590 2500,590 2435,660 2500,660 1225,665 1295,665 1360,665 1300,1305 1365,1305 2425,1305 2490,1305 1300,1400 1365,1400 2425,1400 2490,1400 1300,1495 1365,1495 2425,1495 2490,1495 1070,2035 2740,2045 1070,2145 2740,2145 2740,2250 1070,2255 1250,2370 1345,2375 1410,2375 1890,2385 1955,2385 1345,2470 1410,2470 1890,2480 1955,2480 1250,2550 1345,2565 1410,2565 1890,2575 1955,2575 1345,2650 1410,2650 1890,2650 1955,2650
  other v2: 1730,1565 1760,1565 2240,1565 2270,1565 1730,1595 1760,1595 2240,1595 2270,1595 1730,1625 1760,1625 2240,1625 2270,1625
  other v3: 1708.82,1835.63 1760,1835.63 1811.18,1835.63 2218.82,1835.63 2270,1835.63 2321.18,1835.63 1708.82,1875 1811.18,1875 2218.82,1875 2321.18,1875 1708.82,1914.37 1760,1914.37 1811.18,1914.37 2218.82,1914.37 2270,1914.37 2321.18,1914.37
  other v4: 1657.64,1835.63 1862.36,1835.63 2167.64,1835.63 2372.36,1835.63 1657.64,1875 1862.36,1875 2167.64,1875 2372.36,1875 1657.64,1914.37 1862.36,1914.37 2167.64,1914.37 2372.36,1914.37
HO1: Q1.4 Q2.4 U1.19 | length 1170.7
  Top Layer w15: v2(1500,945) Q2.4@1523.98,945 ; Q1.4@1678.98,1015 v2(1720,1015) ; 1849.57,1727.49 U1.19@1849.57,1758.86 ; 1852.87,1724.12 1852.87,1718.01 1865,1705.88 v2(1865,1705)
  Signal Layer 1 w15: v2(1500,945) 1630,945 1700,1015 v2(1720,1015) 1807.35,1015 1862.87,1070.53 1862.87,1687.87 1865,1690 v2(1865,1705)
HO2: Q5.4 Q6.4 U2.19 | length 1582.3
  Top Layer w15: v2@2071.02,946.02 Q5.4@2120,946.02 ; Q6.4@2271.02,1020 v2(2310,1020) ; U2.19@2359.57,1758.86 2360.93,1757.5 2360.93,1724.96 2380.88,1705 v2(2385,1705)
  Signal Layer 1 w15: v2(2070,945) 2190,945 ; v2(2310,1020) 2310,990 2265,945 2190,945 ; v2(2385,1705) 2385,1745 2369.78,1760.22 2187.87,1760.22 2157.13,1729.47 2157.13,1552.87 2255,1455 2255,1267.35 2234.25,1246.6 2234.25,1039.17 2190,994.92 2190,945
